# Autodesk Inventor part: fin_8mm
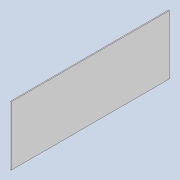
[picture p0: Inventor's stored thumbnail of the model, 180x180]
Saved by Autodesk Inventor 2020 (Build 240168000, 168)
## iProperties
Created: 2021-10
Part Number: fin_8mm
Material: Generic
Document SubType Name: Modeling
Designer: Shuang Peng
Density: 1 g/cm^3
Appearance: Default
Author: Shuang Peng
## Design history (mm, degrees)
sketch "Sketch1"
  geometry: L1 (0, 0)-(0, -8); L2 (-0.025, 0)-(-0.025, -8); L3 (0.025, -8)-(0.025, 0); A1 r 0.025 centre (0, 0) between (0.025, 0) and (-0.025, 0); A2 r 0.025 centre (0, -8) between (-0.025, -8) and (0.025, -8); 1 further point
  constraints: 8 end point, 4 point on circle, 4 tangent, 2 centre point, 1 midpoint, 1 parallel, 1 vertical
  dimensions: "d0" = 8 distance of L1.start L1.end; "d1" = 0.05 diameter of A2
extrude "Extrusion1" new body sketch "Sketch1" distance "d2" = 3; taper "d3" = 0 deg
body "Solid1"
